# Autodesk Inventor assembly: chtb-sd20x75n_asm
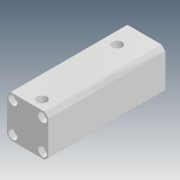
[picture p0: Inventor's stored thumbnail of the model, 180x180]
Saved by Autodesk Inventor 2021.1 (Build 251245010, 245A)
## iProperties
Company: Microsoft
Created: 2018-04
Part Number: chtb-sd20x75n_asm
Description: STEP AP214
Document SubType Name: Assembly
Designer: user
Title: chtb-sd20x75n_asm.STEP
Author: Windows
Revision Number: ÈÎºÎ
Sending System: SolidWorks 2015
Preprocessor: SwSTEP 2.0
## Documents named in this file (4)
- D:\Vault_2016\Projekty\Clamptek\Hydraulic\CHTB\CHTB-20\Inventor\CHTB-SD20x75N\chtb-sd20x75n_asm.iam
- D:\Vault_2016\Projekty\Clamptek\Hydraulic\CHTB\CHTB-20\Inventor\CHTB-SD20x75N\CHTB-SD20X75NBT.ipt
- D:\Vault_2016\Projekty\Clamptek\Hydraulic\CHTB\CHTB-20\Inventor\CHTB-SD20x75N\CHTB-SD20X75NHSG.ipt
- D:\Vault_2016\Projekty\Clamptek\Hydraulic\CHTB\CHTB-20\Inventor\CHTB-SD20x75N\QG.ipt
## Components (3 placed, 3 different names)
1. CHTB-SD20X75NBT_1
2. CHTB-SD20X75NHSG_2
3. QG_3
